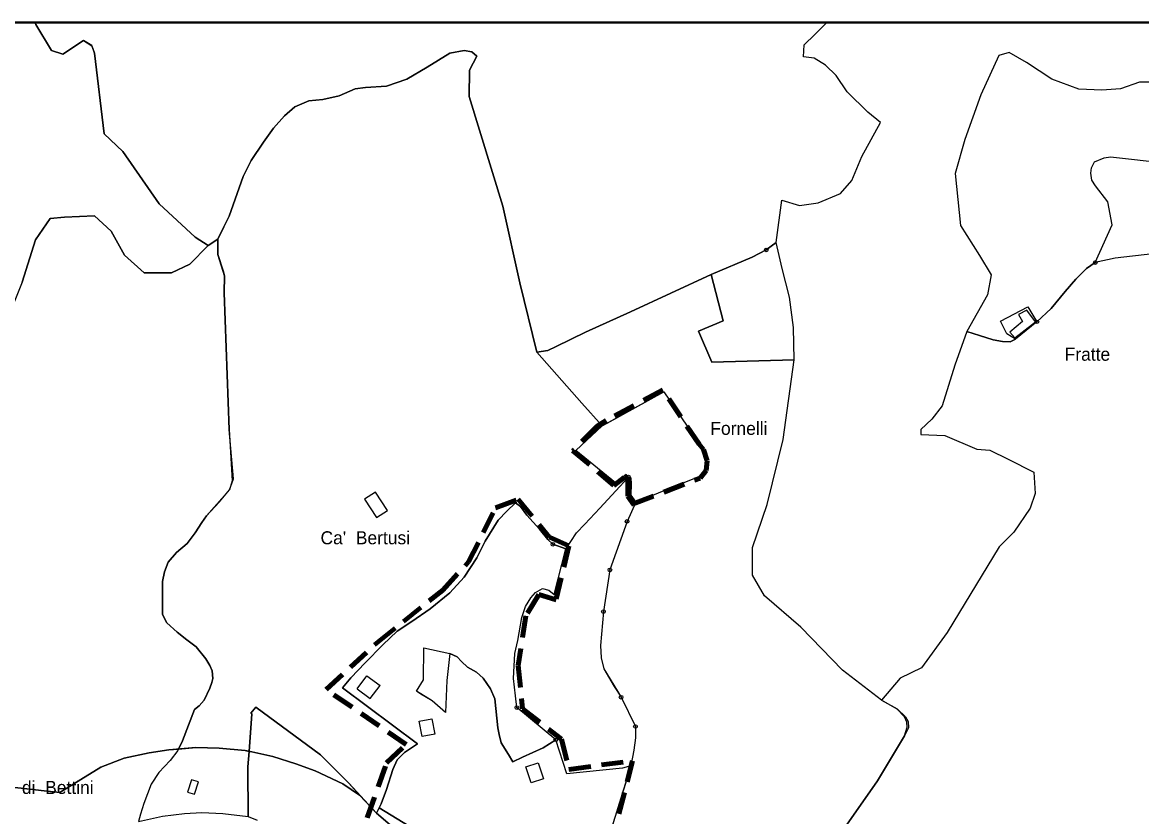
# Model space of a CAD drawing. Extents: x 652791 to 656927, y 889884 to 892405.
# Drawn here: x 655580 to 656439, y 891796 to 892405 of the extents above; entities that cross this region are included whole.
import ezdxf
from ezdxf.enums import TextEntityAlignment as Align

# ---------------------------------------------------------------- set-up
doc = ezdxf.new("R2010")
doc.units = 0
doc.header["$LTSCALE"] = 5.6
doc.header["$PDMODE"] = 32
doc.header["$PDSIZE"] = 2.8
doc.linetypes.add('MEDIUM_DASHED', pattern=[4.5, 3, -1.5])
for name, color, linetype, lineweight in [('12', 7, 'Continuous', 25), ('30', 7, 'Continuous', 25), ('32', 7, 'Continuous', 25), ('33', 7, 'Continuous', 25), ('35', 7, 'Continuous', 25), ('36', 7, 'Continuous', 25), ('37', 7, 'Continuous', 25), ('4', 7, 'Continuous', 25), ('55', 7, 'Continuous', 25), ('6', 7, 'Continuous', 25), ('61', 7, 'Continuous', 35), ('7', 7, 'MEDIUM_DASHED', 100), ('9', 7, 'Continuous', 25)]:
    doc.layers.add(name, color=color, linetype=linetype, lineweight=lineweight)
doc.layers.add('60', color=7, linetype='Continuous')

msp = doc.modelspace()

# ---------------------------------------------------------------- linework, layer by layer
at = {"layer": '12'}
msp.add_lwpolyline([(655888.5, 891925), (655908.32, 891920.64), (655906.06, 891899.99), (655905.14, 891875.37), (655894.95, 891884.37), (655882.68, 891891.78), (655888.24, 891900.55)], close=True, dxfattribs=at)
at = {"layer": '30'}
msp.add_line((655754.3, 891845.65), (655756.37, 891845.22), dxfattribs=at)
for points in [[(655839.18, 891812.21), (655830.8, 891821.22), (655809.14, 891842.89), (655759.39, 891879.59), (655755.78, 891875.07), (655756.39, 891874.36), (655754.3, 891845.65)], [(655754.3, 891845.65), (655753.43, 891833.77), (655753.71, 891795.7), (655760.59, 891793.02)], [(655852.15, 891798.25), (655839.18, 891812.21), (655826.35, 891820.69), (655804.95, 891830.79), (655790.33, 891836.18), (655772.53, 891841.86), (655756.37, 891845.22), (655754.3, 891845.65)], [(655756.37, 891845.22), (655772.53, 891841.86), (655790.33, 891836.18), (655804.95, 891830.79), (655826.35, 891820.69), (655839.18, 891812.21)], [(655930.23, 891691.47), (655930.27, 891695.83), (655926.99, 891704.53), (655908.14, 891731.75), (655894.99, 891744.76), (655889.85, 891750.11), (655887.11, 891763.14), (655881.08, 891773.51), (655866.28, 891786.27), (655852.15, 891798.25)]]:
    msp.add_lwpolyline(points, dxfattribs=at)
at = {"layer": '32'}
msp.add_lwpolyline([(656099.31, 892167.83), (656109.37, 892144.22), (656172.63, 892145.91), (656172.12, 892170.61), (656169.03, 892194.06), (656163.37, 892216.01), (656158.74, 892235.97), (656151.26, 892230.2), (656140.46, 892224.72), (656108.94, 892211.29), (656118.25, 892175.9)], close=True, dxfattribs=at)
at = {"layer": '33'}
for points in [[(655987.43, 892004.52), (655983.69, 892008.08), (655977.1, 892016.06), (655967.5, 892026.71), (655962.64, 892033.37), (655958.73, 892036.22), (655952.07, 892029.83), (655945.56, 892022.98), (655935.6, 892006.88), (655929.12, 891994.19), (655919.31, 891979.32), (655908.36, 891967.26), (655893.34, 891954.97), (655879.16, 891945.27), (655868, 891937.73), (655856.93, 891927.43), (655843.29, 891913.65), (655832.33, 891902.04), (655825.89, 891894.52), (655883.55, 891851.57), (655873.67, 891844.92), (655867.91, 891839.06), (655864.62, 891831.87), (655859.68, 891816.44), (655855.8, 891805.55), (655854.22, 891802.39)], [(655979.56, 891970.6), (655984.24, 891969.22), (655988.33, 891965.86), (655997.31, 892000.97), (655987.43, 892004.52)], [(655966.48, 891956.79), (655970.43, 891963.52), (655974.03, 891967.53), (655979.56, 891970.6)], [(655961.54, 891936.46), (655963.7, 891948.38), (655966.48, 891956.79)], [(655958.26, 891920.66), (655960.6, 891930.61), (655961.54, 891936.46)], [(655964.16, 891841.32), (655956.86, 891837.52), (655953.36, 891843.36), (655947.81, 891852.13), (655946.35, 891858.56), (655945.18, 891863.82), (655942.94, 891885.97), (655939.59, 891893.67), (655933.87, 891901.76), (655928.93, 891906.5), (655922.03, 891910.25), (655917.3, 891914.59), (655913.94, 891918.15), (655908.32, 891920.64), (655906.06, 891899.99), (655905.14, 891875.37), (655894.95, 891884.37), (655886.21, 891889.61), (655882.68, 891891.78), (655888.24, 891900.55), (655888.5, 891925), (655908.32, 891920.64)], [(655908.32, 891920.64), (655913.94, 891918.15), (655917.3, 891914.59), (655922.03, 891910.25)], [(655979.93, 891848.33), (655989.69, 891854.52), (655959.83, 891879.28), (655958.87, 891888.32), (655957.26, 891901.5), (655958.26, 891920.66)], [(655922.03, 891910.25), (655928.93, 891906.5), (655933.87, 891901.76), (655939.59, 891893.67), (655942.94, 891885.97), (655945.18, 891863.82)], [(655945.18, 891863.82), (655946.35, 891858.56), (655947.81, 891852.13)], [(655989.69, 891854.52), (655979.93, 891848.33), (655964.16, 891841.32)], [(656023, 891756.2), (656043.33, 891821.39), (656047.32, 891834.46), (656040.98, 891832.9), (655998.19, 891828.4), (655989.69, 891854.52)], [(655947.81, 891852.13), (655953.36, 891843.36), (655956.86, 891837.52)], [(655956.86, 891837.52), (655964.16, 891841.32), (655979.93, 891848.33)], [(655962.52, 891730.25), (655943.99, 891744.83), (655926.98, 891756.35), (655925.47, 891764.52), (655917.18, 891762.98), (655901.55, 891773.56), (655854.22, 891802.39), (655852.15, 891798.25), (655866.28, 891786.27), (655881.08, 891773.51)], [(655854.22, 891802.39), (655901.55, 891773.56), (655917.18, 891762.98), (655925.47, 891764.52), (655926.98, 891756.35), (655943.99, 891744.83), (655962.52, 891730.25)]]:
    msp.add_lwpolyline(points, dxfattribs=at)
for p in [(655987.43, 892004.52), (655989.69, 891854.52)]:
    msp.add_point(p, dxfattribs=at)
at = {"layer": '35'}
for p, q in [((656044.47, 892022.05), (656031.26, 891984.86)), ((656031.26, 891984.86), (656026.3, 891952.9)), ((656039.83, 891887.16), (656050.8, 891864.74))]:
    msp.add_line(p, q, dxfattribs=at)
for points in [[(655754.3, 891845.65), (655756.39, 891874.36), (655755.78, 891875.07), (655759.39, 891879.59), (655809.14, 891842.89), (655830.8, 891821.22), (655852.15, 891798.25), (655855.8, 891805.55), (655859.68, 891816.44), (655864.62, 891831.87), (655867.91, 891839.06), (655873.67, 891844.92), (655883.55, 891851.57), (655825.89, 891894.52), (655832.33, 891902.04), (655843.29, 891913.65), (655856.93, 891927.43), (655868, 891937.73), (655879.16, 891945.27), (655893.34, 891954.97), (655908.36, 891967.26), (655919.31, 891979.32), (655929.12, 891994.19), (655935.6, 892006.88), (655945.56, 892022.98), (655952.07, 892029.83), (655958.73, 892036.22), (655962.64, 892033.37), (655967.5, 892026.71), (655977.1, 892016.06), (655983.69, 892008.08), (655987.43, 892004.52), (655997.31, 892000.97), (656001.25, 892006.74), (656005.62, 892013.24), (656011.88, 892019.82), (656023.61, 892032.3), (656038.73, 892048.9), (656045.47, 892056.07), (656043.67, 892058.07), (656035.46, 892051.63), (656005, 892076.39), (656025.29, 892095.33), (656009.73, 892112.7), (655975.1, 892151.68), (655962, 892204.93), (655949.13, 892263.8), (655923.19, 892347.74), (655923.37, 892367.98), (655929.17, 892378.91), (655925.23, 892382.1), (655919.47, 892383.03), (655908.34, 892380.98), (655891.08, 892370.39), (655875.3, 892361.11), (655859.71, 892355.72), (655843.58, 892354.65), (655835.83, 892353.87), (655823.43, 892348.44), (655810.9, 892345.51), (655800.19, 892344.57), (655789.34, 892339.91), (655781.59, 892332.94), (655773.03, 892323.59), (655765.32, 892312.78), (655756.02, 892298.82), (655749.82, 892286.41), (655739.14, 892256.07), (655734.91, 892247.88), (655730.45, 892238.34), (655730.45, 892226.71), (655734.33, 892214.3), (655735.55, 892210.32), (655735.1, 892197.24), (655738.97, 892092.57), (655741.43, 892053.04), (655739.31, 892046.15), (655733.52, 892039.49), (655721.68, 892026.19), (655718.06, 892021.09), (655713.02, 892013.38), (655706.76, 892005.17), (655698.55, 891998.12), (655692.1, 891990.88), (655689.38, 891983.24), (655687.99, 891975.96), (655687.83, 891964.63), (655687.8, 891950.52), (655691.32, 891944.32), (655699.02, 891937.11), (655706.51, 891931.31), (655713.8, 891925.74), (655721.15, 891916.55), (655724.13, 891911.49), (655726, 891907.49), (655726.49, 891901.45), (655725.76, 891898.52), (655724.25, 891894.07), (655719.97, 891885.05)], [(656212.68, 891789), (656236.47, 891823.03), (656257.36, 891857.51), (656259.4, 891864.17), (656259.02, 891868.12), (656257.33, 891872.27), (656251.68, 891878.11), (656239.58, 891884.9), (656209.68, 891907.91), (656177.72, 891940.91), (656149.88, 891964.92), (656140.6, 891980.92), (656140.6, 892001.93), (656151.94, 892034.93), (656164.31, 892084.95), (656172.63, 892145.91), (656109.37, 892144.22), (656099.31, 892167.83), (656118.25, 892175.9), (656108.94, 892211.29), (656046.95, 892182.65), (656012.47, 892167.06), (655990.01, 892156.11), (655983.63, 892153.18), (655975.1, 892151.68), (656009.73, 892112.7), (656025.29, 892095.33), (656029.11, 892097.42), (656072.62, 892121.27), (656099.1, 892082.29), (656102.94, 892077.23), (656104.61, 892070.26), (656104.92, 892063.72), (656101.31, 892056.96), (656051.25, 892036.87), (656044.47, 892022.04), (656031.26, 891984.86), (656026.31, 891952.9), (656023.97, 891926.94), (656024.56, 891917.35), (656026.47, 891908.94), (656039.83, 891887.16), (656050.8, 891864.74), (656050.94, 891856), (656049.63, 891846.49), (656047.32, 891834.46), (656023, 891756.2)], [(655979.56, 891970.6), (655984.24, 891969.22), (655988.33, 891965.86), (655997.31, 892000.97), (656001.25, 892006.74), (656005.62, 892013.24), (656011.88, 892019.82), (656023.61, 892032.3), (656038.73, 892048.9), (656045.47, 892056.07)], [(656045.47, 892056.07), (656047.33, 892055.5), (656047.56, 892050.87), (656047.28, 892042.04), (656051.24, 892036.87), (656044.47, 892022.05)], [(655966.48, 891956.79), (655970.43, 891963.52), (655974.03, 891967.53), (655979.56, 891970.6)], [(655961.54, 891936.46), (655963.7, 891948.38), (655966.48, 891956.79)], [(656026.3, 891952.9), (656023.97, 891926.94), (656024.56, 891917.35), (656026.47, 891908.94), (656034.42, 891895.35), (656039.83, 891887.16)], [(655958.26, 891920.66), (655960.6, 891930.61), (655961.54, 891936.46)], [(655959.83, 891879.28), (655958.87, 891888.32), (655957.26, 891901.5), (655958.26, 891920.66)], [(655719.97, 891885.05), (655715.97, 891880.48), (655712.44, 891877.79), (655703.33, 891853.75), (655700.24, 891847.42)], [(656049.63, 891846.49), (656047.32, 891834.46), (656040.98, 891832.9), (655998.19, 891828.4), (655989.69, 891854.52), (655959.83, 891879.28)], [(656050.8, 891864.74), (656050.94, 891856), (656049.63, 891846.49)], [(655700.24, 891847.42), (655699.56, 891846.42), (655693.7, 891838.71), (655685.03, 891829.36), (655679.08, 891820.43), (655673.63, 891805.75), (655670.94, 891797.41), (655669.46, 891791.77), (655687.95, 891796.1)], [(655687.95, 891796.1), (655704.64, 891798.15), (655718.02, 891798.89), (655734.15, 891798.14), (655753.71, 891795.7), (655753.43, 891833.77), (655754.3, 891845.65)], [(655754.3, 891845.65), (655751.28, 891846.27), (655731.29, 891848.24), (655713.48, 891848.65), (655700.24, 891847.42)], [(655700.24, 891847.42), (655713.48, 891848.65), (655731.29, 891848.24), (655751.28, 891846.27), (655754.3, 891845.65)]]:
    msp.add_lwpolyline(points, dxfattribs=at)
for p in [(656045.47, 892056.07), (656044.47, 892022.05), (656031.26, 891984.86), (656026.3, 891952.9), (656039.83, 891887.16), (655959.83, 891879.28), (656050.8, 891864.74)]:
    msp.add_point(p, dxfattribs=at)
at = {"layer": '36'}
msp.add_line((656188.46, 892395.53), (656197.66, 892404.69), dxfattribs=at)
for points in [[(655589.82, 892404.69), (655528.42, 892404.69)], [(655635.64, 892381), (655633.75, 892386.85), (655627.13, 892390.82), (655611.36, 892380.33), (655602.65, 892383.24), (655590.72, 892402.97), (655589.82, 892404.69)], [(656197.66, 892404.69), (656511.01, 892404.69), (656510.85, 892394.11), (656506.27, 892382.25), (656506.27, 892376.25)], [(656288.2, 892087.79), (656312.86, 892077.43), (656322.84, 892076.67), (656336.96, 892069.7), (656356.54, 892059.72), (656357.68, 892043.32), (656353.74, 892032.14), (656341.25, 892013.72), (656330.08, 892002.53), (656290.11, 891936.91), (656270.32, 891909.76), (656254.02, 891901.9), (656239.58, 891884.9), (656209.68, 891907.91), (656177.72, 891940.91), (656149.88, 891964.92), (656140.6, 891980.92), (656140.6, 892001.93), (656151.94, 892034.93), (656164.31, 892084.95), (656172.63, 892145.91), (656172.12, 892170.61), (656169.03, 892194.06), (656163.37, 892216.01), (656158.74, 892235.97), (656163.21, 892268.36), (656176.62, 892264.36), (656191.05, 892266.36), (656208.07, 892273.36), (656216.83, 892283.36), (656224.56, 892301.87), (656239, 892327.87), (656229.2, 892335.88), (656213.22, 892351.38), (656204.97, 892363.88), (656196.72, 892371.89), (656187.96, 892377.39), (656179.71, 892378.39), (656180.21, 892387.53), (656188.46, 892395.53)], [(655580.26, 892205.55), (655590.43, 892238.03), (655601.72, 892254.41), (655612.64, 892255.34), (655635.69, 892256.32), (655648.47, 892244.64), (655658.74, 892226.18), (655673.77, 892212.57), (655694.81, 892212.57), (655708.84, 892219.38), (655723.02, 892233.71), (655713.01, 892239.92), (655685.32, 892265.65), (655657.33, 892305.64), (655642.99, 892319.24), (655635.64, 892381)], [(656473.62, 892358.84), (656437.53, 892358.84), (656423.1, 892353.84), (656408.66, 892352.84), (656391.18, 892353.42), (656370.47, 892361.14), (656350.89, 892373.95), (656337.52, 892381.67), (656329.61, 892379.41), (656315.87, 892349.27), (656303.49, 892314.83), (656296.28, 892288.82), (656300.4, 892248.82), (656314.84, 892225.81), (656323.78, 892211.18), (656321.02, 892195.8), (656305.18, 892167.58), (656295.98, 892141.92), (656286.31, 892110.77), (656278.25, 892100.48)], [(656506.27, 892376.25), (656510.85, 892368.07), (656509.92, 892355.4), (656515.31, 892340.85), (656523.66, 892330.54), (656529.49, 892318.86), (656532.27, 892306.35), (656532.55, 892291.34), (656526.99, 892279.67), (656517.11, 892264.29), (656503.19, 892251.29), (656488.23, 892242.28), (656469.67, 892234.28), (656447.77, 892227.11), (656418.86, 892223.82), (656403.75, 892220.53), (656416.59, 892249.43), (656413.39, 892267.14), (656403.79, 892279.38)], [(656403.22, 892297.65), (656410.57, 892300.86), (656415.46, 892301.61), (656458.95, 892296.71)], [(656400.21, 892288.99), (656400.78, 892293.13), (656403.22, 892297.65)], [(656403.79, 892279.38), (656401.15, 892283.71), (656400.21, 892288.99)], [(656278.25, 892100.48), (656269.75, 892092.5), (656269.93, 892088.54), (656288.2, 892087.79)]]:
    msp.add_lwpolyline(points, dxfattribs=at)
at = {"layer": '37'}
msp.add_line((656358.92, 892175.07), (656342.45, 892161.69), dxfattribs=at)
for points in [[(656197.66, 892404.69), (655589.81, 892404.69), (655590.72, 892402.96), (655602.65, 892383.23), (655611.36, 892380.32), (655627.13, 892390.81)], [(656151.26, 892230.2), (656158.74, 892235.97), (656163.21, 892268.36), (656176.62, 892264.36), (656191.05, 892266.36), (656208.07, 892273.36), (656216.83, 892283.36), (656224.56, 892301.87), (656239, 892327.87), (656229.2, 892335.88), (656213.22, 892351.38), (656204.97, 892363.88), (656196.72, 892371.89), (656187.96, 892377.39), (656179.71, 892378.39), (656180.21, 892387.53), (656188.46, 892395.53), (656197.66, 892404.69)], [(655627.13, 892390.81), (655633.75, 892386.84), (655635.64, 892380.99), (655642.99, 892319.23), (655657.33, 892305.63), (655685.32, 892265.64), (655713.01, 892239.91), (655723.02, 892233.7), (655730.45, 892238.34)], [(655730.45, 892238.34), (655734.91, 892247.88), (655739.14, 892256.07), (655749.82, 892286.41), (655756.02, 892298.82), (655765.32, 892312.78), (655773.03, 892323.59), (655781.59, 892332.94), (655789.34, 892339.91), (655800.19, 892344.57), (655810.9, 892345.51), (655823.43, 892348.44), (655835.83, 892353.87), (655843.58, 892354.65), (655859.71, 892355.72), (655875.3, 892361.11), (655891.08, 892370.39), (655908.34, 892380.98), (655919.47, 892383.03), (655925.23, 892382.1), (655929.17, 892378.91), (655923.37, 892367.98), (655923.19, 892347.74), (655949.13, 892263.8), (655962, 892204.93)], [(656473.62, 892358.84), (656437.53, 892358.84), (656423.1, 892353.84), (656408.66, 892352.84), (656391.18, 892353.42), (656370.47, 892361.14), (656350.89, 892373.95), (656337.52, 892381.67), (656329.61, 892379.41), (656315.87, 892349.27), (656303.49, 892314.83), (656296.28, 892288.82), (656300.4, 892248.82), (656314.84, 892225.81), (656323.78, 892211.18), (656321.02, 892195.8), (656305.18, 892167.58), (656314.98, 892164.64)], [(655590.43, 892238.02), (655580.26, 892205.54), (655568.13, 892175.6), (655561.92, 892170.24), (655553.17, 892172.5), (655549.51, 892194.09), (655543.85, 892219.1), (655532.48, 892236.86), (655522.46, 892251.45), (655517.04, 892272.2), (655520.45, 892300.05), (655523.53, 892317.95), (655520.14, 892326.19)], [(656403.22, 892297.65), (656410.57, 892300.86), (656415.46, 892301.61), (656458.95, 892296.71)], [(656400.21, 892288.99), (656400.78, 892293.13), (656403.22, 892297.65)], [(656403.79, 892279.38), (656401.15, 892283.71), (656400.21, 892288.99)], [(656396.37, 892215.49), (656396.9, 892216.02), (656403.75, 892220.53), (656416.59, 892249.43), (656413.39, 892267.14), (656403.79, 892279.38)], [(656517.11, 892264.29), (656503.19, 892251.29), (656488.23, 892242.28), (656469.67, 892234.28), (656447.77, 892227.11), (656418.86, 892223.82), (656403.75, 892220.53)], [(655719.97, 891885.05), (655724.25, 891894.07), (655725.76, 891898.52), (655726.49, 891901.45), (655726, 891907.49), (655724.13, 891911.49), (655721.15, 891916.55), (655713.8, 891925.74), (655706.51, 891931.31), (655699.02, 891937.11), (655691.32, 891944.32), (655687.8, 891950.52), (655687.83, 891964.63), (655687.99, 891975.96), (655689.38, 891983.24), (655692.1, 891990.88), (655698.55, 891998.12), (655706.76, 892005.17), (655713.02, 892013.38), (655718.06, 892021.09), (655721.68, 892026.19), (655731.7, 892037.05), (655739.31, 892046.15), (655742.28, 892054.6), (655738.97, 892092.57), (655735.1, 892197.24), (655735.55, 892210.32), (655730.45, 892226.71), (655730.45, 892231.59), (655730.45, 892238.34), (655723.02, 892233.7), (655708.84, 892219.37), (655694.81, 892212.56), (655673.77, 892212.56), (655658.74, 892226.17), (655648.47, 892244.63), (655635.69, 892256.31), (655612.64, 892255.33), (655601.72, 892254.4), (655590.43, 892238.02)], [(655983.63, 892153.18), (655990.01, 892156.11), (656012.47, 892167.06), (656046.95, 892182.65), (656108.94, 892211.29), (656140.46, 892224.72), (656151.26, 892230.2)], [(656403.75, 892220.53), (656396.9, 892216.02), (656388.69, 892207.81), (656380.67, 892198.45), (656369.78, 892185.27), (656358.92, 892175.07)], [(656380.67, 892198.45), (656388.69, 892207.81), (656396.37, 892215.49)], [(655962, 892204.93), (655975.1, 892151.68), (655983.63, 892153.18)], [(656358.92, 892175.07), (656369.78, 892185.27), (656380.67, 892198.45)], [(656314.98, 892164.64), (656325.48, 892161.2), (656332.55, 892160.05), (656338.47, 892159.67), (656342.45, 892161.69), (656335.81, 892165.77), (656330.97, 892175.67), (656351.9, 892186.55), (656358.92, 892175.07)], [(656342.45, 892161.69), (656338.47, 892159.67), (656332.55, 892160.05), (656325.48, 892161.2), (656314.98, 892164.64), (656305.18, 892167.58), (656295.98, 892141.92), (656286.31, 892110.77), (656278.25, 892100.48)], [(656278.25, 892100.48), (656269.75, 892092.5), (656269.93, 892088.54), (656288.2, 892087.79)], [(656288.2, 892087.79), (656312.86, 892077.43), (656322.84, 892076.67), (656336.96, 892069.7), (656356.54, 892059.72), (656357.68, 892043.32), (656353.74, 892032.14), (656341.25, 892013.72), (656330.08, 892002.53), (656290.11, 891936.91), (656270.32, 891909.76), (656254.02, 891901.9), (656239.58, 891884.9)], [(655700.24, 891847.42), (655703.33, 891853.75), (655712.44, 891877.79), (655715.97, 891880.48), (655719.97, 891885.05)], [(656239.58, 891884.9), (656251.8, 891878.19), (656258.02, 891872.19), (656260.02, 891868.63), (656260.47, 891863.74), (656257.36, 891857.51), (656236.47, 891823.03), (656212.68, 891789), (656187.83, 891763.23), (656177.5, 891754.21), (656170.25, 891748.49), (656160.57, 891743.21), (656154.2, 891735.29), (656153.25, 891723.59), (656156.3, 891713.28), (656159.36, 891704.5), (656162.03, 891693.05), (656165.84, 891680.45), (656167.75, 891672.44), (656167.75, 891657.93)], [(655430.37, 891825.09), (655456.38, 891823.01), (655490.4, 891821.27), (655520.05, 891820.67), (655546.19, 891820.04), (655561.35, 891819.34), (655579.49, 891817.36), (655597.12, 891815.5), (655608.99, 891814.04), (655625.11, 891824.07), (655640.55, 891833.67), (655658.39, 891840.35), (655677.77, 891844.48), (655692.81, 891846.73), (655700.24, 891847.42)]]:
    msp.add_lwpolyline(points, dxfattribs=at)
for p in [(656151.26, 892230.2), (656403.75, 892220.53), (656358.92, 892175.07)]:
    msp.add_point(p, dxfattribs=at)
at = {"layer": '4'}
for points in [[(656330.96, 892175.67), (656351.89, 892186.55), (656358.91, 892175.07), (656342.44, 892161.69), (656335.8, 892165.77)], [(656351.27, 892184.03), (656344.88, 892180.64), (656347.75, 892175.29), (656338.23, 892167.21), (656342.01, 892162.7), (656357.73, 892175.03)]]:
    msp.add_lwpolyline(points, close=True, dxfattribs=at)
at = {"layer": '55'}
for points in [[(655756.37, 891845.22), (655751.28, 891846.27), (655731.29, 891848.24), (655713.48, 891848.65), (655692.81, 891846.73), (655677.77, 891844.48), (655658.39, 891840.35), (655640.55, 891833.67), (655625.11, 891824.07), (655608.99, 891814.04), (655597.12, 891815.5), (655579.49, 891817.36), (655561.35, 891819.34), (655546.19, 891820.04), (655520.05, 891820.67), (655490.4, 891821.27), (655456.38, 891823.01), (655430.37, 891825.09)], [(655962.52, 891730.25), (655943.99, 891744.83), (655926.98, 891756.35), (655925.47, 891764.52), (655917.18, 891762.98), (655901.55, 891773.56), (655854.22, 891802.39), (655852.15, 891798.25), (655839.18, 891812.21), (655826.35, 891820.69), (655804.95, 891830.79), (655790.33, 891836.18), (655772.53, 891841.86), (655756.37, 891845.22)]]:
    msp.add_lwpolyline(points, dxfattribs=at)
at = {"layer": '6'}
for p, q in [((655837.31, 891893.63), (655844.81, 891903.62)), ((655844.81, 891903.62), (655854.81, 891896.11)), ((655847.31, 891886.12), (655854.81, 891896.11)), ((655837.31, 891893.63), (655847.31, 891886.12))]:
    msp.add_line(p, q, dxfattribs=at)
for points in [[(655843.01, 892039.11), (655852.11, 892024.99), (655860.51, 892030.4), (655851.41, 892044.52)], [(655896.85, 891858.92), (655887.03, 891857.01), (655884.75, 891868.79), (655894.57, 891870.7)], [(655976.2, 891836.92), (655980.23, 891824.56), (655970.71, 891821.46), (655966.69, 891833.83)], [(655710.04, 891823.96), (655707.13, 891814.38), (655712.47, 891812.76), (655715.38, 891822.34)]]:
    msp.add_lwpolyline(points, close=True, dxfattribs=at)
at = {"layer": '61', "lineweight": 40}
msp.add_lwpolyline([(654894.04, 892404.68), (656926.84, 892404.68), (656926.84, 889884.41), (654894.04, 889884.41)], close=True, dxfattribs=at)
at = {"layer": '7'}
msp.add_line((656071.81, 892122.9), (656028.32, 892099.36), dxfattribs=at)
for points in [[(656042.27, 892055.78), (656044.99, 892054.65), (656044.99, 892041.3), (656049.97, 892034.57), (656049.11, 892035.47), (656100.62, 892055.29), (656105.16, 892061.04), (656105.99, 892068.49), (656103.12, 892077.06), (656099.73, 892081.14), (656071.81, 892122.9)], [(656028.32, 892099.36), (656021.46, 892095.17), (656002.56, 892076.05), (656034.35, 892049.67), (656042.27, 892055.78)], [(655844.99, 891794.59), (655859.89, 891836.84), (655874.8, 891850.93), (655813.53, 891893.18), (655853.27, 891929.63), (655902.95, 891969.4), (655922.82, 891990.94), (655943.52, 892032.36), (655960.9, 892038.99), (655984.91, 892009.99), (655999.82, 892003.36), (655989.88, 891961.94), (655976.63, 891966.08), (655966.7, 891949.51), (655960.9, 891911.4), (655964.21, 891878.27), (655994.02, 891855.07), (655999.82, 891831.87), (656048.66, 891838.5), (656027.14, 891754.83)]]:
    msp.add_lwpolyline(points, dxfattribs=at)
at = {"layer": '9'}
msp.add_lwpolyline([(656005, 892076.39), (656025.29, 892095.33), (656072.62, 892121.27), (656099.1, 892082.29), (656102.94, 892077.23), (656104.61, 892070.26), (656104.92, 892063.72), (656101.31, 892056.96), (656051.24, 892036.87), (656047.28, 892042.04), (656047.56, 892050.87), (656047.33, 892055.5), (656045.47, 892056.07), (656043.67, 892058.07), (656035.46, 892051.63)], close=True, dxfattribs=at)

# ---------------------------------------------------------------- texts
at = {"layer": '60'}
for s, p in [('Fratte', (656397.7, 892145.23)), ('Fornelli', (656130.22, 892088.37)), ("Ca'  Bertusi", (655843.52, 892004.47)), ("Ca'  di  Bettini", (655593.97, 891813))]:
    msp.add_text(s, height=10, dxfattribs=at).set_placement(p, align=Align.CENTER)

doc.saveas('drawing.dxf')
